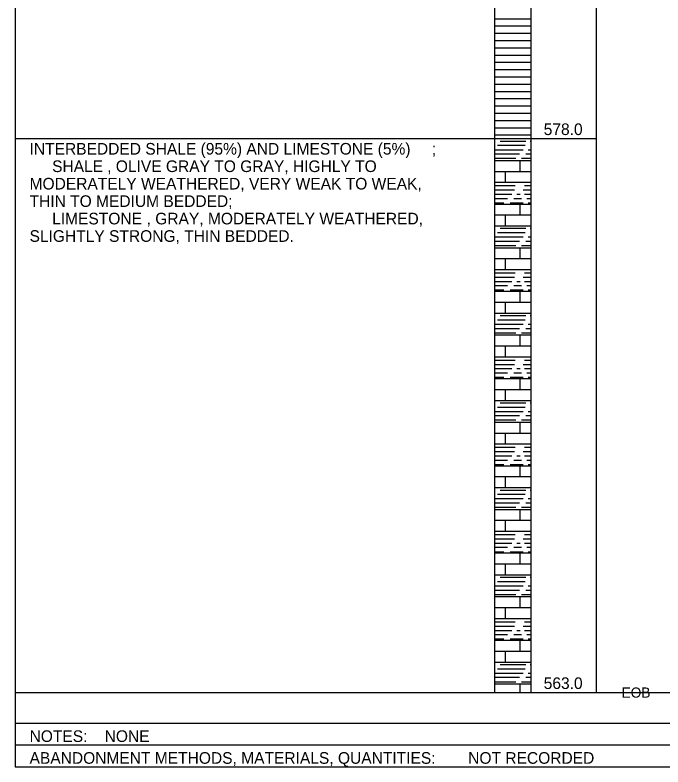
# Model space of a CAD drawing. Extents: x 0 to 0.833, y -0.254 to 0.608.
# Drawn here: x 0 to 0.3715, y -0.2543 to 0.1767 of the extents above; entities that cross this region are included whole.
import ezdxf

# ---------------------------------------------------------------- set-up
doc = ezdxf.new("R2010")
doc.units = 0

msp = doc.modelspace()

# ---------------------------------------------------------------- linework, layer by layer
msp.add_lwpolyline([(0, -0.25414), (0.83333, -0.25414), (0.83333, 0.60833), (0, 0.60833)], close=True)
for points in [[(0.29583, 0.55417), (0.29583, -0.21167)], [(0.29583, 0.55417), (0.29583, -0.21167)], [(0.33333, 0.55417), (0.33333, -0.21167)], [(0.33333, 0.55417), (0.33333, -0.21167)], [(0.275, 0.52917), (0.275, -0.21167)], [(0.275, 0.37042), (0.275, 0.10583)], [(0.275, 0.17458), (0.29583, 0.17458)], [(0.275, 0.17042), (0.29583, 0.17042)], [(0.275, 0.16625), (0.29583, 0.16625)], [(0.275, 0.16208), (0.29583, 0.16208)], [(0.275, 0.15792), (0.29583, 0.15792)], [(0.275, 0.15375), (0.29583, 0.15375)], [(0.275, 0.14958), (0.29583, 0.14958)], [(0.275, 0.14542), (0.29583, 0.14542)], [(0.275, 0.14125), (0.29583, 0.14125)], [(0.275, 0.13708), (0.29583, 0.13708)], [(0.275, 0.13292), (0.29583, 0.13292)], [(0.275, 0.12875), (0.29583, 0.12875)], [(0.275, 0.12458), (0.29583, 0.12458)], [(0.275, 0.12042), (0.29583, 0.12042)], [(0.275, 0.11625), (0.29583, 0.11625)], [(0.275, 0.11208), (0.29583, 0.11208)], [(0.275, 0.10792), (0.29583, 0.10792)], [(0, 0.10583), (0.275, 0.10583)], [(0.275, 0.10583), (0.29583, 0.10583)], [(0.275, 0.10583), (0.29583, 0.10583)], [(0.275, 0.10583), (0.275, -0.21167)], [(0.27825, 0.10442), (0.293, 0.10442)], [(0.29542, 0.10442), (0.29583, 0.10442)], [(0.29583, 0.10583), (0.33333, 0.10583)], [(0.275, 0.0995), (0.29133, 0.0995)], [(0.27667, 0.102), (0.29258, 0.102)], [(0.29417, 0.0995), (0.29583, 0.0995)], [(0.275, 0.09708), (0.28933, 0.09708)], [(0.293, 0.09708), (0.29583, 0.09708)], [(0.275, 0.09458), (0.28725, 0.09458)], [(0.275, 0.09333), (0.29583, 0.09333)], [(0.28958, 0.08708), (0.28958, 0.09333)], [(0.2905, 0.09458), (0.29583, 0.09458)], [(0.275, 0.08708), (0.29583, 0.08708)], [(0.28125, 0.08083), (0.28125, 0.08708)], [(0.275, 0.08083), (0.29583, 0.08083)], [(0.275, 0.07892), (0.28683, 0.07892)], [(0.29217, 0.07892), (0.29583, 0.07892)], [(0.275, 0.07642), (0.28642, 0.07642)], [(0.275, 0.074), (0.28483, 0.074)], [(0.28767, 0.074), (0.28967, 0.074)], [(0.29133, 0.07642), (0.29583, 0.07642)], [(0.29217, 0.074), (0.29583, 0.074)], [(0.275, 0.07158), (0.28233, 0.07158)], [(0.275, 0.06908), (0.28033, 0.06908)], [(0.284, 0.06908), (0.29133, 0.06908)], [(0.286, 0.07158), (0.2905, 0.07158)], [(0.29342, 0.07158), (0.29583, 0.07158)], [(0.29417, 0.06908), (0.29583, 0.06908)], [(0.275, 0.06833), (0.29583, 0.06833)], [(0.28958, 0.06208), (0.28958, 0.06833)], [(0.275, 0.06208), (0.29583, 0.06208)], [(0.28125, 0.05583), (0.28125, 0.06208)], [(0.275, 0.05583), (0.29583, 0.05583)], [(0.27667, 0.052), (0.29258, 0.052)], [(0.27825, 0.05442), (0.293, 0.05442)], [(0.29542, 0.05442), (0.29583, 0.05442)], [(0.275, 0.0495), (0.29133, 0.0495)], [(0.29417, 0.0495), (0.29583, 0.0495)], [(0.275, 0.04708), (0.28933, 0.04708)], [(0.275, 0.04458), (0.28725, 0.04458)], [(0.275, 0.04333), (0.29583, 0.04333)], [(0.28958, 0.03708), (0.28958, 0.04333)], [(0.2905, 0.04458), (0.29583, 0.04458)], [(0.293, 0.04708), (0.29583, 0.04708)], [(0.275, 0.03708), (0.29583, 0.03708)], [(0.28125, 0.03083), (0.28125, 0.03708)], [(0.275, 0.03083), (0.29583, 0.03083)], [(0.275, 0.02892), (0.28683, 0.02892)], [(0.275, 0.02642), (0.28642, 0.02642)], [(0.29133, 0.02642), (0.29583, 0.02642)], [(0.29217, 0.02892), (0.29583, 0.02892)], [(0.275, 0.024), (0.28483, 0.024)], [(0.275, 0.02158), (0.28233, 0.02158)], [(0.286, 0.02158), (0.2905, 0.02158)], [(0.28767, 0.024), (0.28967, 0.024)], [(0.29217, 0.024), (0.29583, 0.024)], [(0.29342, 0.02158), (0.29583, 0.02158)], [(0.275, 0.01908), (0.28033, 0.01908)], [(0.275, 0.01833), (0.29583, 0.01833)], [(0.284, 0.01908), (0.29133, 0.01908)], [(0.28958, 0.01208), (0.28958, 0.01833)], [(0.29417, 0.01908), (0.29583, 0.01908)], [(0.275, 0.01208), (0.29583, 0.01208)], [(0.28125, 0.00583), (0.28125, 0.01208)], [(0.275, 0.00583), (0.29583, 0.00583)], [(0.27825, 0.00442), (0.293, 0.00442)], [(0.29542, 0.00442), (0.29583, 0.00442)], [(0.27667, 0.002), (0.29258, 0.002)], [(0.275, -0.0005), (0.29133, -0.0005)], [(0.275, -0.00292), (0.28933, -0.00292)], [(0.293, -0.00292), (0.29583, -0.00292)], [(0.29417, -0.0005), (0.29583, -0.0005)], [(0.275, -0.00542), (0.28725, -0.00542)], [(0.275, -0.00667), (0.29583, -0.00667)], [(0.28958, -0.01292), (0.28958, -0.00667)], [(0.2905, -0.00542), (0.29583, -0.00542)], [(0.275, -0.01292), (0.29583, -0.01292)], [(0.28125, -0.01917), (0.28125, -0.01292)], [(0.275, -0.01917), (0.29583, -0.01917)], [(0.275, -0.02108), (0.28683, -0.02108)], [(0.29217, -0.02108), (0.29583, -0.02108)], [(0.275, -0.02358), (0.28642, -0.02358)], [(0.29133, -0.02358), (0.29583, -0.02358)], [(0.275, -0.026), (0.28483, -0.026)], [(0.275, -0.02842), (0.28233, -0.02842)], [(0.286, -0.02842), (0.2905, -0.02842)], [(0.28767, -0.026), (0.28967, -0.026)], [(0.29217, -0.026), (0.29583, -0.026)], [(0.29342, -0.02842), (0.29583, -0.02842)], [(0.275, -0.03092), (0.28033, -0.03092)], [(0.275, -0.03167), (0.29583, -0.03167)], [(0.284, -0.03092), (0.29133, -0.03092)], [(0.28958, -0.03792), (0.28958, -0.03167)], [(0.29417, -0.03092), (0.29583, -0.03092)], [(0.275, -0.03792), (0.29583, -0.03792)], [(0.28125, -0.04417), (0.28125, -0.03792)], [(0.275, -0.04417), (0.29583, -0.04417)], [(0.27825, -0.04558), (0.293, -0.04558)], [(0.29542, -0.04558), (0.29583, -0.04558)], [(0.275, -0.0505), (0.29133, -0.0505)], [(0.27667, -0.048), (0.29258, -0.048)], [(0.29417, -0.0505), (0.29583, -0.0505)], [(0.275, -0.05292), (0.28933, -0.05292)], [(0.275, -0.05542), (0.28725, -0.05542)], [(0.2905, -0.05542), (0.29583, -0.05542)], [(0.293, -0.05292), (0.29583, -0.05292)], [(0.275, -0.05667), (0.29583, -0.05667)], [(0.28958, -0.06292), (0.28958, -0.05667)], [(0.275, -0.06292), (0.29583, -0.06292)], [(0.28125, -0.06917), (0.28125, -0.06292)], [(0.275, -0.06917), (0.29583, -0.06917)], [(0.275, -0.07108), (0.28683, -0.07108)], [(0.29217, -0.07108), (0.29583, -0.07108)], [(0.275, -0.07358), (0.28642, -0.07358)], [(0.275, -0.076), (0.28483, -0.076)], [(0.28767, -0.076), (0.28967, -0.076)], [(0.29133, -0.07358), (0.29583, -0.07358)], [(0.29217, -0.076), (0.29583, -0.076)], [(0.275, -0.07842), (0.28233, -0.07842)], [(0.275, -0.08092), (0.28033, -0.08092)], [(0.275, -0.08167), (0.29583, -0.08167)], [(0.284, -0.08092), (0.29133, -0.08092)], [(0.286, -0.07842), (0.2905, -0.07842)], [(0.28958, -0.08792), (0.28958, -0.08167)], [(0.29342, -0.07842), (0.29583, -0.07842)], [(0.29417, -0.08092), (0.29583, -0.08092)], [(0.275, -0.08792), (0.29583, -0.08792)], [(0.28125, -0.09417), (0.28125, -0.08792)], [(0.275, -0.09417), (0.29583, -0.09417)], [(0.27667, -0.098), (0.29258, -0.098)], [(0.27825, -0.09558), (0.293, -0.09558)], [(0.29542, -0.09558), (0.29583, -0.09558)], [(0.275, -0.1005), (0.29133, -0.1005)], [(0.275, -0.10292), (0.28933, -0.10292)], [(0.293, -0.10292), (0.29583, -0.10292)], [(0.29417, -0.1005), (0.29583, -0.1005)], [(0.275, -0.10542), (0.28725, -0.10542)], [(0.275, -0.10667), (0.29583, -0.10667)], [(0.28958, -0.11292), (0.28958, -0.10667)], [(0.2905, -0.10542), (0.29583, -0.10542)], [(0.275, -0.11292), (0.29583, -0.11292)], [(0.28125, -0.11917), (0.28125, -0.11292)], [(0.275, -0.11917), (0.29583, -0.11917)], [(0.275, -0.12108), (0.28683, -0.12108)], [(0.275, -0.12358), (0.28642, -0.12358)], [(0.29133, -0.12358), (0.29583, -0.12358)], [(0.29217, -0.12108), (0.29583, -0.12108)], [(0.275, -0.126), (0.28483, -0.126)], [(0.275, -0.12842), (0.28233, -0.12842)], [(0.286, -0.12842), (0.2905, -0.12842)], [(0.28767, -0.126), (0.28967, -0.126)], [(0.29217, -0.126), (0.29583, -0.126)], [(0.29342, -0.12842), (0.29583, -0.12842)], [(0.275, -0.13092), (0.28033, -0.13092)], [(0.275, -0.13167), (0.29583, -0.13167)], [(0.284, -0.13092), (0.29133, -0.13092)], [(0.28958, -0.13792), (0.28958, -0.13167)], [(0.29417, -0.13092), (0.29583, -0.13092)], [(0, -0.14164), (0, -0.25414), (0.83333, -0.25414), (0.83333, -0.14164)], [(0.275, -0.13792), (0.29583, -0.13792)], [(0.28125, -0.14417), (0.28125, -0.13792)], [(0.275, -0.14417), (0.29583, -0.14417)], [(0.27825, -0.14558), (0.293, -0.14558)], [(0.29542, -0.14558), (0.29583, -0.14558)], [(0.275, -0.1505), (0.29133, -0.1505)], [(0.27667, -0.148), (0.29258, -0.148)], [(0.29417, -0.1505), (0.29583, -0.1505)], [(0.275, -0.15292), (0.28933, -0.15292)], [(0.293, -0.15292), (0.29583, -0.15292)], [(0.275, -0.15542), (0.28725, -0.15542)], [(0.275, -0.15667), (0.29583, -0.15667)], [(0.28958, -0.16292), (0.28958, -0.15667)], [(0.2905, -0.15542), (0.29583, -0.15542)], [(0.275, -0.16292), (0.29583, -0.16292)], [(0.28125, -0.16917), (0.28125, -0.16292)], [(0.275, -0.16917), (0.29583, -0.16917)], [(0.275, -0.17108), (0.28683, -0.17108)], [(0.29217, -0.17108), (0.29583, -0.17108)], [(0.275, -0.17358), (0.28642, -0.17358)], [(0.275, -0.176), (0.28483, -0.176)], [(0.28767, -0.176), (0.28967, -0.176)], [(0.29133, -0.17358), (0.29583, -0.17358)], [(0.29217, -0.176), (0.29583, -0.176)], [(0.275, -0.17842), (0.28233, -0.17842)], [(0.275, -0.18092), (0.28033, -0.18092)], [(0.284, -0.18092), (0.29133, -0.18092)], [(0.286, -0.17842), (0.2905, -0.17842)], [(0.29342, -0.17842), (0.29583, -0.17842)], [(0.29417, -0.18092), (0.29583, -0.18092)], [(0.275, -0.18167), (0.29583, -0.18167)], [(0.28958, -0.18792), (0.28958, -0.18167)], [(0.275, -0.18792), (0.29583, -0.18792)], [(0.28125, -0.19417), (0.28125, -0.18792)], [(0.275, -0.19417), (0.29583, -0.19417)], [(0.27667, -0.198), (0.29258, -0.198)], [(0.27825, -0.19558), (0.293, -0.19558)], [(0.29542, -0.19558), (0.29583, -0.19558)], [(0.275, -0.2005), (0.29133, -0.2005)], [(0.29417, -0.2005), (0.29583, -0.2005)], [(0.275, -0.20292), (0.28933, -0.20292)], [(0.275, -0.20542), (0.28725, -0.20542)], [(0.275, -0.20667), (0.29583, -0.20667)], [(0.28958, -0.21167), (0.28958, -0.20667)], [(0.2905, -0.20542), (0.29583, -0.20542)], [(0.293, -0.20292), (0.29583, -0.20292)], [(0, -0.21167), (0.275, -0.21167)], [(0.275, -0.21167), (0.29583, -0.21167)], [(0.275, -0.21167), (0.29583, -0.21167)], [(0.29583, -0.21167), (0.33333, -0.21167)], [(0.33333, -0.21167), (0.37917, -0.21167)], [(0, -0.22914), (0.83333, -0.22914)], [(0, -0.24164), (0.83333, -0.24164)]]:
    msp.add_lwpolyline(points)

# ---------------------------------------------------------------- texts
for s, height, p in [('578.0', 0.006667, (0.30316, 0.10788)), ('INTERBEDDED SHALE (95%) AND LIMESTONE (5%)', 0.0066667, (0.00833, 0.09667)), (';', 0.00667, (0.23898, 0.09667)), ('SHALE', 0.006667, (0.02127, 0.08667)), (', OLIVE GRAY TO GRAY, HIGHLY TO', 0.0066667, (0.05284, 0.08667)), ('MODERATELY WEATHERED, VERY WEAK TO WEAK,', 0.0066667, (0.00833, 0.07667)), ('THIN TO MEDIUM BEDDED;', 0.0066667, (0.00833, 0.06667)), ('LIMESTONE', 0.006667, (0.02127, 0.05667)), (', GRAY, MODERATELY WEATHERED,', 0.0066667, (0.07544, 0.05667)), ('SLIGHTLY STRONG, THIN BEDDED.', 0.0066667, (0.00833, 0.04667)), ('563.0', 0.006667, (0.30316, -0.20962)), ('EOB', 0.005833, (0.34786, -0.21458)), ('NOTES:', 0.006667, (0.00833, -0.23998)), ('NONE', 0.006667, (0.05139, -0.23998)), ('ABANDONMENT METHODS, MATERIALS, QUANTITIES:', 0.0066667, (0.00833, -0.25248)), ('NOT RECORDED', 0.0066667, (0.25986, -0.25248))]:
    msp.add_text(s, height=height).set_placement(p)

doc.saveas('drawing.dxf')
